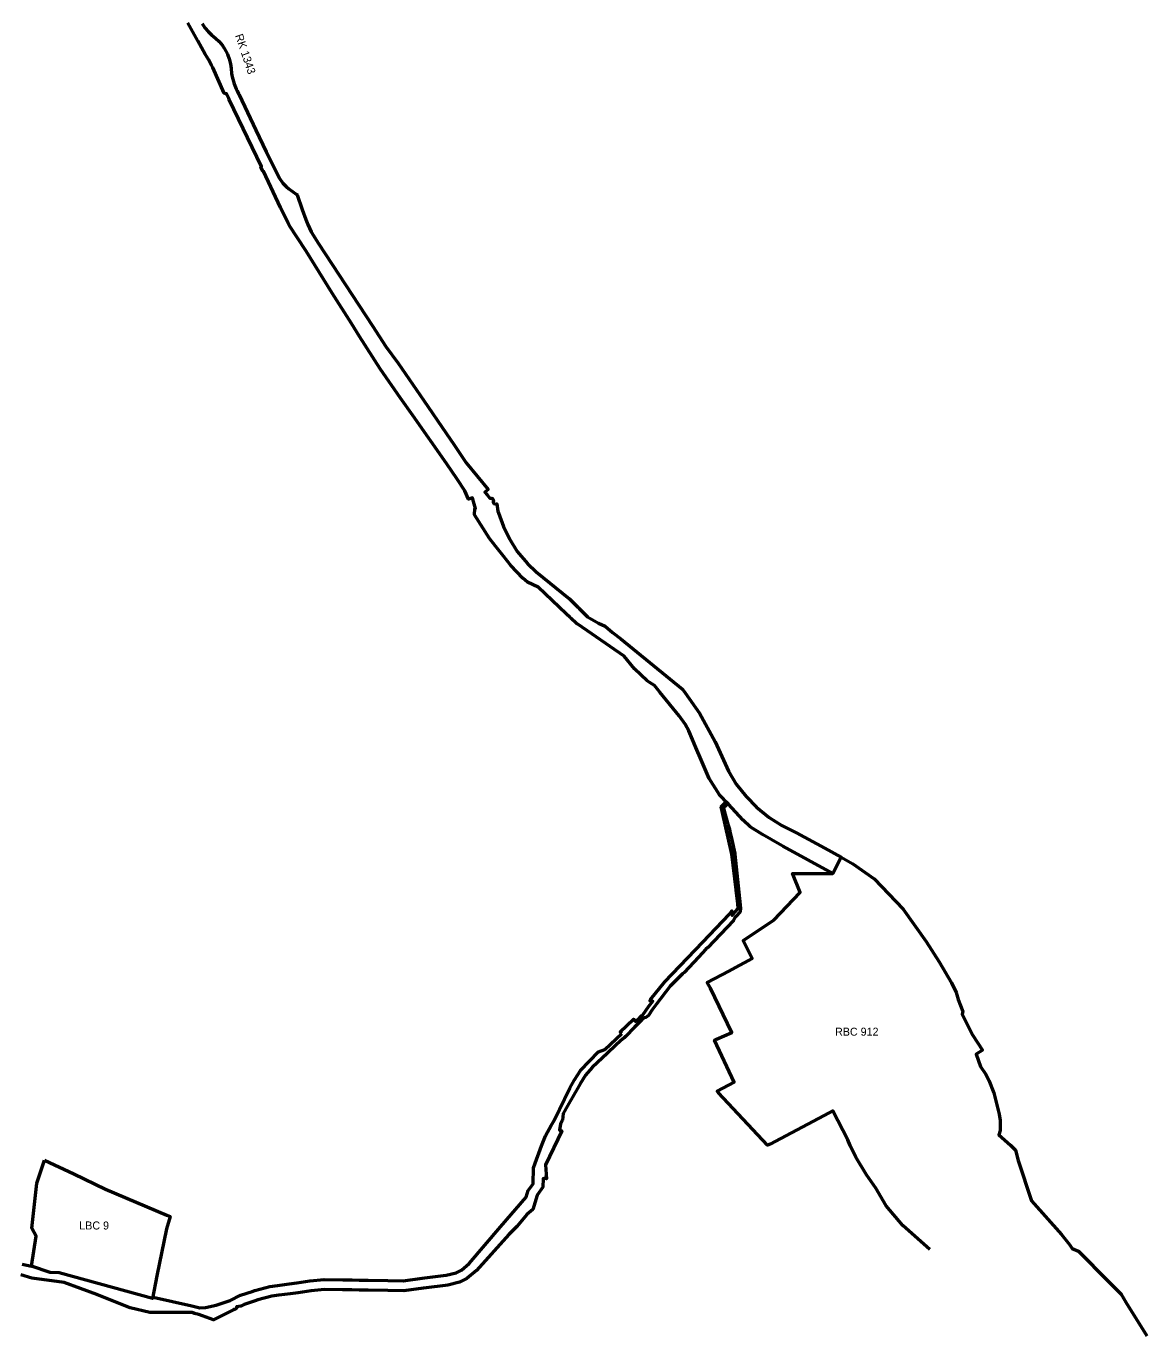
# Model space of a CAD drawing. Extents: x -650276 to -642570, y -1074314 to -1066553.
# Drawn here: x -647403 to -645724, y -1073097 to -1071134 of the extents above; entities that cross this region are included whole.
import ezdxf
from ezdxf.enums import TextEntityAlignment as Align

# ---------------------------------------------------------------- set-up
doc = ezdxf.new("R2010")
doc.units = 0
doc.header["$LTSCALE"] = 4.8
for name, color, linetype, lineweight in [('15', 7, 'Continuous', 53), ('19', 7, 'Continuous', 53), ('23', 7, 'Continuous', 53), ('27', 7, 'Continuous', 53)]:
    doc.layers.add(name, color=color, linetype=linetype, lineweight=lineweight)
doc.layers.add('63', color=7, linetype='Continuous')

msp = doc.modelspace()

# ---------------------------------------------------------------- linework, layer by layer
at = {"layer": '15'}
msp.add_lwpolyline([(-646048.986, -1072967.984), (-646089.39, -1072931.92), (-646114.5, -1072902.8), (-646129.91, -1072876.24), (-646143.99, -1072856.11), (-646159.73, -1072829.79), (-646168.17, -1072812.07), (-646171.72, -1072803.51), (-646194.287, -1072760.209), (-646199.72, -1072763.1), (-646288.27, -1072810.22), (-646292.17, -1072811.6), (-646365.52, -1072733.03), (-646367.72, -1072730.68), (-646342.08, -1072717.43), (-646371.66, -1072654.2), (-646368.51, -1072652.81), (-646345.75, -1072642.79), (-646377.84, -1072576.29), (-646380.47, -1072571.51), (-646382.41, -1072568.01), (-646350.18, -1072550.59), (-646340.16, -1072545.17), (-646320.62, -1072534.6), (-646315.32, -1072532.01), (-646328.45, -1072504.81), (-646282.47, -1072474.34), (-646243.17, -1072432.88), (-646254.75, -1072404.25), (-646194.19, -1072404.62), (-646181.907, -1072379.974), (-646164.02, -1072390), (-646132.34, -1072412.37), (-646088.86, -1072457.93), (-646054.33, -1072506.16), (-646034.83, -1072536.97), (-646016.46, -1072568.07), (-646009.27, -1072582.89), (-646006.21, -1072593.04), (-645999.14, -1072611.29), (-646000.45, -1072615.28), (-645984.88, -1072646.21), (-645969.97, -1072669.21), (-645979.44, -1072675.29), (-645972.67, -1072693.74), (-645965.19, -1072704.94), (-645960.61, -1072714.42), (-645953.06, -1072733.07), (-645944.81, -1072765.04), (-645943.38, -1072774.7), (-645943.65, -1072789.47), (-645945.37, -1072795.9), (-645927.96, -1072811.61), (-645920.56, -1072819.2), (-645916.48, -1072834.69), (-645896.61, -1072895.14), (-645851.64, -1072945.67), (-645839.57, -1072960.36), (-645835.46, -1072966.49), (-645825.96, -1072970.48), (-645781.57, -1073015.6), (-645761.93, -1073034.98), (-645754.82, -1073046.89), (-645723.602, -1073097.398)], dxfattribs=at)
at = {"layer": '19'}
for points in [[(-646394.24, -1072163.81), (-646370.83, -1072206.8), (-646350.46, -1072250.81), (-646339.07, -1072270.33), (-646324.17, -1072289.15), (-646308.74, -1072304.97), (-646289.9, -1072320.26), (-646270.62, -1072332.33), (-646248.46, -1072343.52), (-646206.07, -1072366.43), (-646181.907, -1072379.974), (-646194.19, -1072404.62), (-646269.41, -1072363.38), (-646273.54, -1072361), (-646299.75, -1072345.87), (-646318.09, -1072334.2), (-646328.57, -1072324.62), (-646351.15, -1072300), (-646364.12, -1072286.56), (-646379.86, -1072262.05), (-646391.77, -1072233.91), (-646399.6, -1072215.39), (-646404.67, -1072203.42), (-646410.14, -1072190.49), (-646415.84, -1072180.43), (-646424.56, -1072167.96), (-646453.42, -1072132.4), (-646461.56, -1072122.36), (-646469.41, -1072117.44), (-646472.72, -1072115.38), (-646491.69, -1072097.45), (-646507.28, -1072078.4), (-646576.63, -1072030.7), (-646578.46, -1072029.62), (-646586.85, -1072021.71), (-646587.71, -1072020.9), (-646588.12, -1072020.51), (-646593.88, -1072015.08), (-646636.01, -1071975.35), (-646651.94, -1071967.82), (-646659.02, -1071961.92), (-646676.92, -1071942.93), (-646688.02, -1071928.75), (-646699.77, -1071913.72), (-646708.81, -1071902.16), (-646731.16, -1071866.9), (-646730.82, -1071857.31), (-646730.1, -1071857.16), (-646733.03, -1071846.65), (-646734.49, -1071841.44), (-646740.35, -1071843.3), (-646746.05, -1071830.54), (-646757.15, -1071813.15), (-646773.23, -1071789.58), (-646823.68, -1071717.76), (-646842.09, -1071691.69), (-646872.61, -1071647.71), (-646903.67, -1071599.34), (-646916, -1071580.13), (-646944.58, -1071534.7), (-646983.8, -1071471.4), (-646997.05, -1071451.02), (-647008.5, -1071433.35), (-647010.73, -1071429.74), (-647021.47, -1071407.2), (-647022.03, -1071406.03), (-647047.61, -1071351.39), (-647048.59, -1071351.85), (-647051.77, -1071345.17), (-647050.89, -1071344.72), (-647098.97, -1071244.31), (-647099.74, -1071242.71), (-647102.06, -1071237.84), (-647102.72, -1071236.47), (-647102.97, -1071235.92), (-647103.31, -1071235.22), (-647104.17, -1071235.6), (-647106.7, -1071234.45), (-647123.7, -1071196.19), (-647125.44, -1071192.58), (-647130.1, -1071184.33), (-647135.21, -1071176.44), (-647146.28, -1071156.35), (-647161.13, -1071129.3)], [(-647139.72, -1071130.15), (-647135.45, -1071136.55), (-647130.77, -1071142.19), (-647125.39, -1071147.43), (-647119.65, -1071152.23), (-647114.14, -1071157.35), (-647109.3, -1071163.15), (-647106.48, -1071167.29), (-647103.94, -1071171.55), (-647101.72, -1071176.06), (-647098.97, -1071183.12), (-647097.18, -1071190.47), (-647096.16, -1071197.88), (-647095.44, -1071205.33), (-647094.61, -1071210.4), (-647091.74, -1071220.44), (-647088.5, -1071228.08), (-647087.93, -1071229.39), (-647087.3, -1071231.11), (-647085.13, -1071235.62), (-647084.13, -1071237.12), (-647059.06, -1071290.09), (-647043.61, -1071322.57), (-647040.39, -1071329.27), (-647024.36, -1071361.64), (-647018.53, -1071369.49), (-647013.75, -1071374.67), (-647009.87, -1071378.03), (-646998.54, -1071385.9), (-646997.58, -1071386.56), (-646996.97, -1071387.15), (-646989.58, -1071409.27), (-646984.18, -1071424.12), (-646981.06, -1071431.57), (-646976.09, -1071442.66), (-646965.35, -1071460.17), (-646884.4, -1071583.42), (-646864.39, -1071614.36), (-646845.66, -1071639.56), (-646807.19, -1071695.29), (-646773.79, -1071744.44), (-646761.95, -1071761.85), (-646743.9, -1071788.63), (-646710.82, -1071828.79), (-646715.81, -1071832.61), (-646712.47, -1071836.84), (-646708.56, -1071841.8), (-646706.02, -1071842.28), (-646705.52, -1071841.88), (-646702.75, -1071845), (-646703.44, -1071848.03), (-646702.16, -1071849.6), (-646698.84, -1071850.56), (-646697.91, -1071850.24), (-646696.3, -1071861.21), (-646695.43, -1071863.67), (-646688.11, -1071884.22), (-646678.98, -1071902.58), (-646667.19, -1071921.65), (-646652.07, -1071939.58), (-646638.81, -1071952.21), (-646588.96, -1071992.55), (-646575.92, -1072005.55), (-646575.57, -1072005.9), (-646574.48, -1072006.99), (-646565.98, -1072015.45), (-646565.01, -1072016.41), (-646561.99, -1072019.42), (-646545.56, -1072029.37), (-646535.68, -1072033.89), (-646524.34, -1072042.92), (-646512.21, -1072052.57), (-646419.55, -1072128.03), (-646415.61, -1072133.6), (-646394.24, -1072163.81)]]:
    msp.add_lwpolyline(points, dxfattribs=at)
at = {"layer": '23'}
msp.add_lwpolyline([(-647375.92, -1072833.99), (-647331.82, -1072854.49), (-647284.75, -1072877.79), (-647284.75, -1072877.79), (-647192.718, -1072916.582), (-647187.445, -1072918.804), (-647192.93, -1072936.82), (-647207.58, -1073007.44), (-647213.99, -1073041.45), (-647353.78, -1073003.1), (-647367.45, -1073002.47), (-647395.47, -1072993.25), (-647388.62, -1072948.03), (-647394.87, -1072936.08), (-647387.64, -1072868.69)], close=True, dxfattribs=at)
at = {"layer": '27'}
for points in [[(-646510.28, -1072644.42), (-646513.209, -1072641.935), (-646493.229, -1072622.74), (-646490.11, -1072626.15), (-646483.71, -1072620.35), (-646480.37, -1072617.18), (-646479.13, -1072616.26), (-646469.93, -1072603.28), (-646464.22, -1072595.84), (-646468.689, -1072595.119), (-646467.379, -1072593.42), (-646445.877, -1072566.771), (-646389.081, -1072507.297), (-646349.101, -1072465.372), (-646345.829, -1072460.475), (-646345.36, -1072467.29), (-646343.44, -1072465.25), (-646336.87, -1072457.3), (-646336.29, -1072457.22), (-646336.01, -1072456.23), (-646336.75, -1072450.07), (-646339.15, -1072430.13), (-646339.27, -1072429.13), (-646345.73, -1072375.51), (-646360.3, -1072310.87), (-646361.734, -1072304.631), (-646353.892, -1072297.158), (-646351.15, -1072300), (-646358.28, -1072306.16), (-646357.09, -1072310.35), (-646351.47, -1072330.27), (-646349.31, -1072337.93), (-646348.49, -1072341.51), (-646345.6, -1072354.14), (-646341, -1072374.27), (-646341.29, -1072375.31), (-646333.205, -1072451.289), (-646332.68, -1072456.19), (-646333.34, -1072461.67), (-646339.94, -1072469.58), (-646340.51, -1072469.67), (-646343.13, -1072475.03), (-646352.53, -1072484.78), (-646372.79, -1072505.81), (-646381.81, -1072515.17), (-646384.41, -1072517.86), (-646395.71, -1072529.8), (-646417.32, -1072552.64), (-646419.42, -1072554.86), (-646438.05, -1072573.49), (-646459.19, -1072600.85), (-646465.09, -1072608.61), (-646470.33, -1072617.33), (-646474.8, -1072620.09), (-646477.06, -1072620.67), (-646480.43, -1072623.86), (-646486.62, -1072629.97), (-646491.42, -1072634.69), (-646505.26, -1072648.68), (-646507.21, -1072650.52), (-646512.3, -1072655.3), (-646519.93, -1072662.47), (-646531.95, -1072673.77), (-646554.85, -1072695.37), (-646565.04, -1072706.87), (-646573.04, -1072719.85), (-646575.17, -1072723.31), (-646591.82, -1072752.54), (-646598.51, -1072764.27), (-646599.281, -1072774.132)], [(-647213.588, -1073039.315), (-647213.218, -1073039.42), (-647154.999, -1073052.287), (-647143.312, -1073055.421), (-647134.596, -1073054.974), (-647118.513, -1073051.327), (-647097.466, -1073044.268), (-647082.267, -1073036.684), (-647064.784, -1073030.747), (-647060.677, -1073029.351), (-647037.971, -1073023.24), (-647026.763, -1073021.811), (-647009.402, -1073019.582), (-646997.824, -1073018.092), (-646978.077, -1073014.931), (-646956.919, -1073012.775), (-646928.807, -1073013.313), (-646914.796, -1073013.573), (-646904.131, -1073013.793), (-646890.523, -1073014.073), (-646861.07, -1073014.672), (-646838.25, -1073014.938), (-646809.778, -1073011.019), (-646773.9, -1073006.461), (-646758.883, -1073002.885), (-646751.061, -1072999.106), (-646739.241, -1072988.798), (-646692.432, -1072934.135), (-646653.846, -1072889.44), (-646650.798, -1072879.828), (-646643.574, -1072869.57), (-646642.939, -1072845.68), (-646640.313, -1072838.394), (-646631.08, -1072812.68), (-646624.81, -1072797.42), (-646616.6, -1072782.31), (-646612.11, -1072774.56), (-646588.659, -1072726.214), (-646581.578, -1072713.897), (-646572.611, -1072699.551), (-646545.372, -1072671.533), (-646535.97, -1072668.39), (-646510.28, -1072644.42)], [(-646599.281, -1072774.132), (-646602.497, -1072779.637), (-646603.99, -1072788.9), (-646600.37, -1072790.04), (-646625.02, -1072841.21), (-646623.25, -1072862.05), (-646623.95, -1072857.6), (-646623.67, -1072862.03), (-646628.36, -1072861.71), (-646628.7, -1072874.5), (-646637.2, -1072886.57), (-646644.06, -1072908.21), (-646652.76, -1072915.66), (-646668.09, -1072933.43), (-646680.07, -1072945.74), (-646728.558, -1072999.384), (-646742.721, -1073011.735), (-646753.824, -1073017.1), (-646771.21, -1073021.24), (-646807.81, -1073025.89), (-646837.31, -1073029.95), (-646861.31, -1073029.67), (-646890.83, -1073029.07), (-646904.44, -1073028.79), (-646915.09, -1073028.57), (-646929.09, -1073028.31), (-646956.3, -1073027.79), (-646976.13, -1073029.81), (-646995.68, -1073032.94), (-647007.49, -1073034.46), (-647024.86, -1073036.69), (-647035.06, -1073037.99), (-647056.31, -1073043.71), (-647059.96, -1073044.95), (-647076.48, -1073050.56), (-647081.61, -1073053.092), (-647081.66, -1073052.93), (-647088.34, -1073053.92), (-647087.96, -1073056.29), (-647090.83, -1073057.72), (-647092.67, -1073058), (-647092.58, -1073058.59), (-647117.73, -1073070.84), (-647122.68, -1073073.23), (-647144.47, -1073065.23), (-647150.95, -1073063.78), (-647154.77, -1073062.68), (-647218.06, -1073062.37), (-647247.46, -1073055.63), (-647263.8, -1073049), (-647297.53, -1073035.3), (-647346.22, -1073017.52), (-647394.782, -1073011.002), (-647411.34, -1073005.89)], [(-647409.484, -1072990.206), (-647395.47, -1072993.25), (-647395.47, -1072993.25)]]:
    msp.add_lwpolyline(points, dxfattribs=at)

# ---------------------------------------------------------------- texts
at = {"layer": '63'}
msp.add_text('RK 1343', height=12, rotation=288.63, dxfattribs=at).set_placement((-647080.392, -1071177.786), align=Align.CENTER)
for s, p in [('RBC 912', (-646158.336, -1072647.538)), ('LBC 9', (-647301.531, -1072938.022))]:
    msp.add_text(s, height=12, dxfattribs=at).set_placement(p, align=Align.CENTER)

doc.saveas('drawing.dxf')
